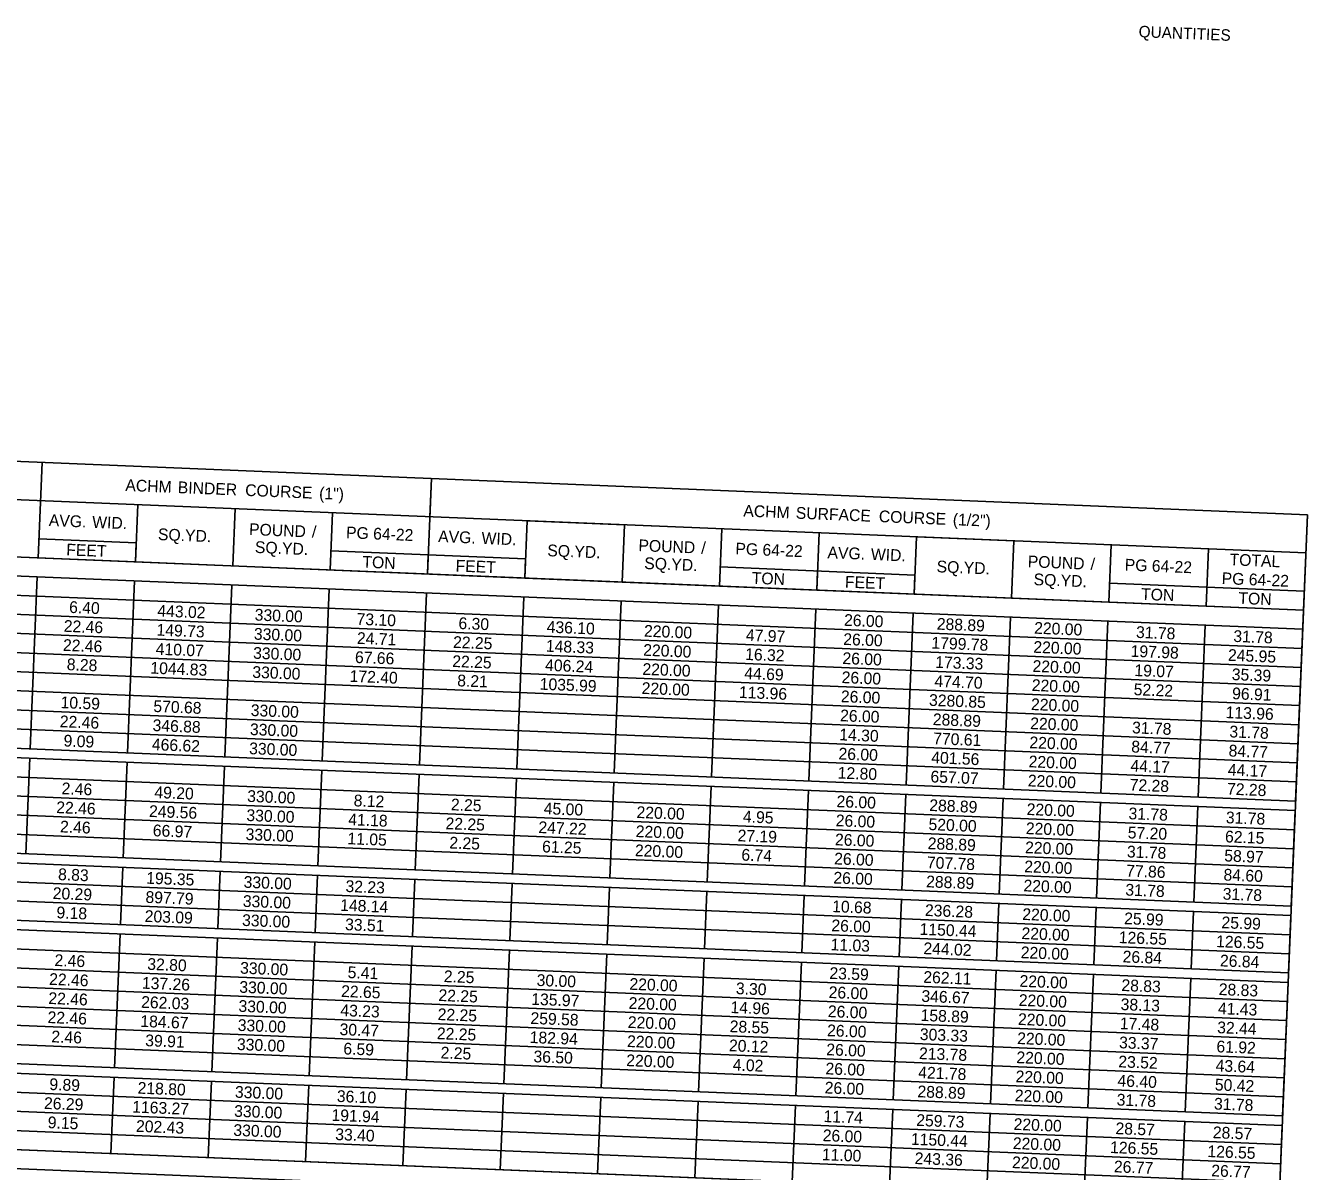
# Model space of a CAD drawing. Extents: x 1164179 to 1171425, y 1655958 to 1657208.
# Drawn here: x 1168859 to 1169513, y 1656436 to 1657021 of the extents above; entities that cross this region are included whole.
import ezdxf

# ---------------------------------------------------------------- set-up
doc = ezdxf.new("R2010")
doc.units = 0
doc.layers.add('Default', color=7, linetype='Continuous')
doc.layers.add('R_Grid', color=7, linetype='Continuous')

msp = doc.modelspace()

# ---------------------------------------------------------------- linework, layer by layer
at = {"layer": 'Default'}
for p, q in [((1168026.37, 1656832.93), (1169513.44, 1656771.41)), ((1168865.55, 1656749.42), (1168867.57, 1656798.13)), ((1168419.62, 1656797.14), (1169512.63, 1656751.93)), ((1168024.36, 1656784.22), (1169511.42, 1656722.7)), ((1169064.28, 1656741.2), (1169066.3, 1656789.91)), ((1169065.49, 1656770.42), (1169066.3, 1656789.91)), ((1168023.96, 1656774.48), (1169511.02, 1656712.96)), ((1168915.23, 1656747.37), (1168916.44, 1656776.59)), ((1168964.92, 1656745.31), (1168966.13, 1656774.54)), ((1169014.6, 1656743.25), (1169015.81, 1656772.48)), ((1169491.27, 1656235.62), (1169513.44, 1656771.41)), ((1169507.39, 1656625.29), (1169513.44, 1656771.41)), ((1168023.55, 1656764.74), (1169510.62, 1656703.22)), ((1169113.96, 1656739.14), (1169115.17, 1656768.37)), ((1169115.17, 1656768.37), (1169164.86, 1656766.31)), ((1169163.65, 1656737.09), (1169164.86, 1656766.31)), ((1168865.95, 1656759.16), (1168915.64, 1656757.11)), ((1169213.33, 1656735.03), (1169214.54, 1656764.26)), ((1169263.01, 1656732.98), (1169264.22, 1656762.2)), ((1169312.69, 1656730.92), (1169313.9, 1656760.15)), ((1169313.9, 1656760.15), (1169363.59, 1656758.09)), ((1169362.38, 1656728.87), (1169363.59, 1656758.09)), ((1168023.15, 1656754.99), (1169510.22, 1656693.48)), ((1168766.19, 1656753.53), (1168915.23, 1656747.37)), ((1168915.23, 1656747.37), (1168915.64, 1656757.11)), ((1169015, 1656753), (1169114.37, 1656748.89)), ((1169412.06, 1656726.81), (1169413.27, 1656756.04)), ((1169461.74, 1656724.76), (1169462.95, 1656753.98)), ((1168022.75, 1656745.25), (1169509.81, 1656683.74)), ((1168915.23, 1656747.37), (1169113.96, 1656739.14)), ((1169064.28, 1656741.2), (1169064.68, 1656750.94)), ((1169113.96, 1656739.14), (1169114.37, 1656748.89)), ((1168861.52, 1656652), (1168865.15, 1656739.68)), ((1168861.52, 1656652), (1168865.15, 1656739.68)), ((1169113.96, 1656739.14), (1169312.69, 1656730.92)), ((1169213.73, 1656744.78), (1169313.1, 1656740.66)), ((1169263.01, 1656732.98), (1169263.42, 1656742.72)), ((1169312.69, 1656730.92), (1169313.1, 1656740.66)), ((1168022.34, 1656735.51), (1169509.41, 1656673.99)), ((1168911.2, 1656649.95), (1168914.83, 1656737.62)), ((1168911.2, 1656649.95), (1168914.83, 1656737.62)), ((1168960.89, 1656647.89), (1168964.51, 1656735.57)), ((1168960.89, 1656647.89), (1168964.51, 1656735.57)), ((1169010.57, 1656645.84), (1169014.2, 1656733.51)), ((1169010.57, 1656645.84), (1169014.2, 1656733.51)), ((1169412.46, 1656736.55), (1169511.83, 1656732.44)), ((1168021.94, 1656725.77), (1169509.01, 1656664.25)), ((1169060.25, 1656643.78), (1169063.88, 1656731.46)), ((1169060.25, 1656643.78), (1169063.88, 1656731.46)), ((1169109.93, 1656641.73), (1169113.56, 1656729.4)), ((1169109.93, 1656641.73), (1169113.56, 1656729.4)), ((1169159.62, 1656639.67), (1169163.24, 1656727.35)), ((1169159.62, 1656639.67), (1169163.24, 1656727.35)), ((1169209.3, 1656637.62), (1169212.93, 1656725.29)), ((1169209.3, 1656637.62), (1169212.93, 1656725.29)), ((1169312.69, 1656730.92), (1169511.42, 1656722.7)), ((1169258.98, 1656635.56), (1169262.61, 1656723.24)), ((1169258.98, 1656635.56), (1169262.61, 1656723.24)), ((1169308.66, 1656633.51), (1169312.29, 1656721.18)), ((1169308.66, 1656633.51), (1169312.29, 1656721.18)), ((1169358.35, 1656631.45), (1169361.97, 1656719.13)), ((1169358.35, 1656631.45), (1169361.97, 1656719.13)), ((1168021.54, 1656716.03), (1169508.6, 1656654.51)), ((1169408.03, 1656629.4), (1169411.66, 1656717.07)), ((1169408.03, 1656629.4), (1169411.66, 1656717.07)), ((1169457.71, 1656627.34), (1169461.34, 1656715.02)), ((1169457.71, 1656627.34), (1169461.34, 1656715.02)), ((1168021.13, 1656706.29), (1169508.2, 1656644.77)), ((1168020.73, 1656696.54), (1169507.8, 1656635.03)), ((1168020.33, 1656686.8), (1169507.39, 1656625.29)), ((1168020.33, 1656686.8), (1169507.39, 1656625.29)), ((1168020.13, 1656681.93), (1169507.19, 1656620.41)), ((1168019.72, 1656672.19), (1169506.79, 1656610.67)), ((1168019.32, 1656662.45), (1169506.39, 1656600.93)), ((1168018.92, 1656652.71), (1169505.98, 1656591.19)), ((1168859.31, 1656598.42), (1168861.32, 1656647.13)), ((1168859.31, 1656598.42), (1168861.32, 1656647.13)), ((1168018.52, 1656642.97), (1169505.58, 1656581.45)), ((1168908.99, 1656596.37), (1168911, 1656645.08)), ((1168908.99, 1656596.37), (1168911, 1656645.08)), ((1168958.67, 1656594.31), (1168960.69, 1656643.02)), ((1168958.67, 1656594.31), (1168960.69, 1656643.02)), ((1169008.35, 1656592.26), (1169010.37, 1656640.97)), ((1169008.35, 1656592.26), (1169010.37, 1656640.97)), ((1169058.04, 1656590.2), (1169060.05, 1656638.91)), ((1169058.04, 1656590.2), (1169060.05, 1656638.91)), ((1169107.72, 1656588.15), (1169109.73, 1656636.86)), ((1169107.72, 1656588.15), (1169109.73, 1656636.86)), ((1169157.4, 1656586.09), (1169159.42, 1656634.8)), ((1169157.4, 1656586.09), (1169159.42, 1656634.8)), ((1168017.91, 1656628.35), (1169504.98, 1656566.84)), ((1168018.11, 1656633.22), (1169505.18, 1656571.71)), ((1169207.08, 1656584.04), (1169209.1, 1656632.75)), ((1169207.08, 1656584.04), (1169209.1, 1656632.75)), ((1169256.77, 1656581.98), (1169258.78, 1656630.69)), ((1169256.77, 1656581.98), (1169258.78, 1656630.69)), ((1169306.45, 1656579.93), (1169308.46, 1656628.64)), ((1169306.45, 1656579.93), (1169308.46, 1656628.64)), ((1169356.13, 1656577.87), (1169358.15, 1656626.58)), ((1169356.13, 1656577.87), (1169358.15, 1656626.58)), ((1169405.81, 1656575.82), (1169407.83, 1656624.53)), ((1169405.81, 1656575.82), (1169407.83, 1656624.53)), ((1169455.5, 1656573.76), (1169457.51, 1656622.47)), ((1169455.5, 1656573.76), (1169457.51, 1656622.47)), ((1168017.51, 1656618.61), (1169504.57, 1656557.09)), ((1168362.48, 1656618.98), (1169505.18, 1656571.71)), ((1169505.18, 1656571.71), (1169507.19, 1656620.41)), ((1168017.11, 1656608.87), (1169504.17, 1656547.35)), ((1168016.7, 1656599.13), (1169503.77, 1656537.61)), ((1168016.5, 1656594.26), (1169503.57, 1656532.74)), ((1168907.58, 1656562.27), (1168908.79, 1656591.5)), ((1168907.58, 1656562.27), (1168908.79, 1656591.5)), ((1168957.26, 1656560.22), (1168958.47, 1656589.44)), ((1168957.26, 1656560.22), (1168958.47, 1656589.44)), ((1168016.1, 1656584.52), (1169503.16, 1656523)), ((1168361.07, 1656584.88), (1169503.77, 1656537.61)), ((1169006.94, 1656558.16), (1169008.15, 1656587.39)), ((1169006.94, 1656558.16), (1169008.15, 1656587.39)), ((1169056.63, 1656556.11), (1169057.83, 1656585.33)), ((1169056.63, 1656556.11), (1169057.83, 1656585.33)), ((1169106.31, 1656554.05), (1169107.52, 1656583.28)), ((1169106.31, 1656554.05), (1169107.52, 1656583.28)), ((1168015.69, 1656574.77), (1169502.76, 1656513.26)), ((1169155.99, 1656552), (1169157.2, 1656581.22)), ((1169155.99, 1656552), (1169157.2, 1656581.22)), ((1169205.67, 1656549.94), (1169206.88, 1656579.17)), ((1169205.67, 1656549.94), (1169206.88, 1656579.17)), ((1169255.36, 1656547.89), (1169256.56, 1656577.11)), ((1169255.36, 1656547.89), (1169256.56, 1656577.11)), ((1169305.04, 1656545.83), (1169306.25, 1656575.06)), ((1169305.04, 1656545.83), (1169306.25, 1656575.06)), ((1169354.72, 1656543.78), (1169355.93, 1656573)), ((1169354.72, 1656543.78), (1169355.93, 1656573)), ((1169404.4, 1656541.72), (1169405.61, 1656570.95)), ((1169404.4, 1656541.72), (1169405.61, 1656570.95)), ((1169454.09, 1656539.67), (1169455.29, 1656568.89)), ((1169454.09, 1656539.67), (1169455.29, 1656568.89)), ((1168015.29, 1656565.03), (1169502.36, 1656503.51)), ((1169503.77, 1656537.61), (1169504.98, 1656566.84)), ((1168014.89, 1656555.29), (1169501.95, 1656493.77)), ((1168904.56, 1656489.21), (1168907.38, 1656557.4)), ((1168904.56, 1656489.21), (1168907.38, 1656557.4)), ((1168954.24, 1656487.16), (1168957.06, 1656555.35)), ((1168954.24, 1656487.16), (1168957.06, 1656555.35)), ((1169003.92, 1656485.1), (1169006.74, 1656553.29)), ((1169003.92, 1656485.1), (1169006.74, 1656553.29)), ((1169053.6, 1656483.05), (1169056.42, 1656551.24)), ((1169053.6, 1656483.05), (1169056.42, 1656551.24)), ((1169103.29, 1656480.99), (1169106.11, 1656549.18)), ((1169103.29, 1656480.99), (1169106.11, 1656549.18)), ((1168014.49, 1656545.55), (1169501.55, 1656484.03)), ((1169152.97, 1656478.93), (1169155.79, 1656547.13)), ((1169152.97, 1656478.93), (1169155.79, 1656547.13)), ((1169202.65, 1656476.88), (1169205.47, 1656545.07)), ((1169202.65, 1656476.88), (1169205.47, 1656545.07)), ((1169252.33, 1656474.82), (1169255.15, 1656543.02)), ((1169252.33, 1656474.82), (1169255.15, 1656543.02)), ((1168014.08, 1656535.81), (1169501.15, 1656474.29)), ((1169302.02, 1656472.77), (1169304.84, 1656540.96)), ((1169302.02, 1656472.77), (1169304.84, 1656540.96)), ((1169351.7, 1656470.71), (1169354.52, 1656538.91)), ((1169351.7, 1656470.71), (1169354.52, 1656538.91)), ((1169401.38, 1656468.66), (1169404.2, 1656536.85)), ((1169401.38, 1656468.66), (1169404.2, 1656536.85)), ((1169451.06, 1656466.6), (1169453.88, 1656534.79)), ((1169451.06, 1656466.6), (1169453.88, 1656534.79)), ((1169500.75, 1656464.55), (1169503.57, 1656532.74)), ((1168013.68, 1656526.07), (1169500.75, 1656464.55)), ((1168013.48, 1656521.19), (1169500.54, 1656459.68)), ((1168013.08, 1656511.45), (1169500.14, 1656449.94)), ((1168358.05, 1656511.82), (1169500.75, 1656464.55)), ((1168012.67, 1656501.71), (1169499.74, 1656440.19)), ((1168012.27, 1656491.97), (1169499.33, 1656430.45)), ((1168902.74, 1656445.37), (1168904.35, 1656484.34)), ((1168902.74, 1656445.37), (1168904.35, 1656484.34)), ((1168011.87, 1656482.23), (1169498.93, 1656420.71)), ((1168952.42, 1656443.32), (1168954.04, 1656482.29)), ((1168952.42, 1656443.32), (1168954.04, 1656482.29)), ((1169002.11, 1656441.26), (1169003.72, 1656480.23)), ((1169002.11, 1656441.26), (1169003.72, 1656480.23)), ((1169051.79, 1656439.21), (1169053.4, 1656478.17)), ((1169051.79, 1656439.21), (1169053.4, 1656478.17)), ((1168011.46, 1656472.49), (1169498.53, 1656410.97)), ((1169101.47, 1656437.15), (1169103.08, 1656476.12)), ((1169101.47, 1656437.15), (1169103.08, 1656476.12)), ((1169151.15, 1656435.1), (1169152.77, 1656474.06)), ((1169151.15, 1656435.1), (1169152.77, 1656474.06)), ((1169200.84, 1656433.04), (1169202.45, 1656472.01)), ((1169200.84, 1656433.04), (1169202.45, 1656472.01)), ((1169250.52, 1656430.99), (1169252.13, 1656469.95)), ((1169250.52, 1656430.99), (1169252.13, 1656469.95)), ((1169300.2, 1656428.93), (1169301.81, 1656467.9)), ((1169300.2, 1656428.93), (1169301.81, 1656467.9)), ((1169349.88, 1656426.88), (1169351.5, 1656465.84)), ((1169349.88, 1656426.88), (1169351.5, 1656465.84)), ((1169399.57, 1656424.82), (1169401.18, 1656463.79)), ((1169399.57, 1656424.82), (1169401.18, 1656463.79)), ((1169449.25, 1656422.77), (1169450.86, 1656461.73)), ((1169449.25, 1656422.77), (1169450.86, 1656461.73)), ((1169497.32, 1656381.74), (1169500.54, 1656459.68)), ((1168853.06, 1656447.43), (1169300.2, 1656428.93))]:
    msp.add_line(p, q, dxfattribs=at)

# ---------------------------------------------------------------- texts
for s, p in [('ACHM', (1168910.02, 1656783.61)), (' BINDER', (1168934.55, 1656782.6)), (' COURSE', (1168968.95, 1656781.17)), (' (1")', (1169006.7, 1656779.61)), ('AVG.', (1168870.95, 1656765.71)), ('ACHM', (1169225.46, 1656770.56)), (' SURFACE', (1169249.99, 1656769.55)), (' COURSE', (1169292.39, 1656767.79)), (' (1/2")', (1169330.14, 1656766.23)), (' WID.', (1168890.85, 1656764.89)), ('SQ.YD.', (1168926.65, 1656758.53)), ('POUND', (1168973.18, 1656761.11)), (' /', (1169003.01, 1656759.87)), ('PG', (1169022.67, 1656759.44)), (' 64-22', (1169034.26, 1656758.96)), ('SQ.YD.', (1168976.14, 1656751.98)), ('AVG.', (1169069.68, 1656757.49)), (' WID.', (1169089.58, 1656756.67)), ('POUND', (1169171.91, 1656752.89)), ('FEET', (1168879.85, 1656750.71)), ('SQ.YD.', (1169125.38, 1656750.31)), (' /', (1169201.74, 1656751.65)), ('PG', (1169221.4, 1656751.21)), (' 64-22', (1169232.99, 1656750.73)), ('AVG.', (1169268.41, 1656749.27)), (' WID.', (1169288.31, 1656748.45)), ('TOTAL', (1169473.63, 1656745.66)), ('TON', (1169031.01, 1656744.45)), ('FEET', (1169078.58, 1656742.48)), ('SQ.YD.', (1169174.87, 1656743.76)), ('SQ.YD.', (1169324.11, 1656742.09)), ('POUND', (1169370.64, 1656744.67)), (' /', (1169400.47, 1656743.43)), ('PG', (1169420.13, 1656742.99)), (' 64-22', (1169431.72, 1656742.51)), ('TON', (1169229.74, 1656736.23)), ('FEET', (1169277.31, 1656734.26)), ('SQ.YD.', (1169373.6, 1656735.53)), ('PG', (1169469.61, 1656736.07)), (' 64-22', (1169481.2, 1656735.59)), ('TON', (1169428.47, 1656728.01)), ('TON', (1169478.16, 1656725.95)), ('6.40', (1168881.32, 1656721.37)), ('443.02', (1168926.36, 1656719.51)), ('330.00', (1168976.02, 1656717.45)), ('73.10', (1169028.04, 1656715.3)), ('6.30', (1169080.05, 1656713.15)), ('26.00', (1169276.85, 1656714.77)), ('288.89', (1169324.19, 1656712.81)), ('22.46', (1168878.57, 1656711.73)), ('149.73', (1168925.93, 1656709.77)), ('330.00', (1168975.62, 1656707.71)), ('436.10', (1169125.07, 1656711.29)), ('220.00', (1169174.75, 1656709.23)), ('47.97', (1169226.75, 1656707.08)), ('220.00', (1169373.89, 1656710.75)), ('31.78', (1169425.88, 1656708.6)), ('31.78', (1169475.56, 1656706.55)), ('22.46', (1168878.17, 1656701.98)), ('410.07', (1168925.52, 1656700.02)), ('24.71', (1169028.2, 1656705.54)), ('22.25', (1169077.28, 1656703.51)), ('148.33', (1169124.66, 1656701.55)), ('26.00', (1169276.45, 1656705.02)), ('1799.78', (1169321.46, 1656703.16)), ('220.00', (1169373.48, 1656701.01)), ('330.00', (1168975.22, 1656697.97)), ('67.66', (1169027.22, 1656695.82)), ('22.25', (1169076.88, 1656693.76)), ('220.00', (1169174.35, 1656699.49)), ('16.32', (1169226.38, 1656697.34)), ('26.00', (1169276.04, 1656695.28)), ('173.33', (1169323.39, 1656693.32)), ('197.98', (1169423.15, 1656698.96)), ('245.95', (1169472.82, 1656696.9)), ('8.28', (1168880.09, 1656692.15)), ('1044.83', (1168922.79, 1656690.38)), ('330.00', (1168974.82, 1656688.23)), ('406.24', (1169124.27, 1656691.8)), ('220.00', (1169173.95, 1656689.75)), ('44.69', (1169225.94, 1656687.6)), ('220.00', (1169373.08, 1656691.27)), ('19.07', (1169425.08, 1656689.12)), ('35.39', (1169474.76, 1656687.06)), ('172.40', (1169024.5, 1656686.17)), ('8.21', (1169079.41, 1656683.9)), ('1035.99', (1169121.52, 1656682.16)), ('220.00', (1169173.55, 1656680.01)), ('26.00', (1169275.64, 1656685.54)), ('474.70', (1169323, 1656683.58)), ('220.00', (1169372.68, 1656681.53)), ('113.96', (1169223.22, 1656677.95)), ('26.00', (1169275.24, 1656675.8)), ('3280.85', (1169320.23, 1656673.94)), ('52.22', (1169424.71, 1656679.37)), ('96.91', (1169474.94, 1656677.3)), ('10.59', (1168876.96, 1656672.76)), ('570.68', (1168924.31, 1656670.8)), ('330.00', (1168974.01, 1656668.74)), ('220.00', (1169372.28, 1656671.78)), ('113.96', (1169471.63, 1656667.67)), ('22.46', (1168876.56, 1656663.02)), ('346.88', (1168923.91, 1656661.06)), ('26.00', (1169274.84, 1656666.06)), ('288.89', (1169322.17, 1656664.1)), ('220.00', (1169371.87, 1656662.04)), ('330.00', (1168973.61, 1656659)), ('14.30', (1169274.43, 1656656.32)), ('770.61', (1169322.36, 1656654.33)), ('31.78', (1169423.87, 1656659.89)), ('31.78', (1169473.55, 1656657.84)), ('9.09', (1168878.48, 1656653.18)), ('466.62', (1168923.54, 1656651.31)), ('330.00', (1168973.2, 1656649.26)), ('220.00', (1169371.47, 1656652.3)), ('84.77', (1169423.47, 1656650.15)), ('84.77', (1169473.15, 1656648.1)), ('26.00', (1169274.03, 1656646.57)), ('401.56', (1169321.37, 1656644.62)), ('220.00', (1169371.07, 1656642.56)), ('12.80', (1169273.63, 1656636.83)), ('657.07', (1169320.97, 1656634.87)), ('44.17', (1169423.07, 1656640.41)), ('44.17', (1169472.75, 1656638.35)), ('2.46', (1168877.48, 1656628.82)), ('220.00', (1169370.66, 1656632.82)), ('72.28', (1169422.66, 1656630.67)), ('72.28', (1169472.34, 1656628.61)), ('49.20', (1168924.84, 1656626.87)), ('330.00', (1168972.2, 1656624.91)), ('8.12', (1169026.56, 1656622.66)), ('26.00', (1169273.02, 1656622.22)), ('22.46', (1168874.74, 1656619.18)), ('249.56', (1168922.1, 1656617.22)), ('330.00', (1168971.79, 1656615.16)), ('2.25', (1169076.18, 1656620.6)), ('45.00', (1169123.57, 1656618.64)), ('220.00', (1169170.93, 1656616.69)), ('288.89', (1169320.36, 1656620.26)), ('220.00', (1169370.06, 1656618.21)), ('31.78', (1169422.05, 1656616.05)), ('2.46', (1168876.67, 1656609.34)), ('41.18', (1169023.79, 1656613.01)), ('22.25', (1169073.45, 1656610.96)), ('247.22', (1169120.86, 1656609)), ('4.95', (1169225.23, 1656614.44)), ('26.00', (1169272.62, 1656612.48)), ('520.00', (1169319.97, 1656610.52)), ('220.00', (1169369.66, 1656608.46)), ('31.78', (1169471.74, 1656614)), ('66.97', (1168924.02, 1656607.38)), ('330.00', (1168971.39, 1656605.42)), ('11.05', (1169023.37, 1656603.27)), ('220.00', (1169170.52, 1656606.94)), ('27.19', (1169222.52, 1656604.79)), ('26.00', (1169272.22, 1656602.74)), ('57.20', (1169421.67, 1656606.31)), ('62.15', (1169471.32, 1656604.26)), ('2.25', (1169075.38, 1656601.12)), ('61.25', (1169122.73, 1656599.16)), ('220.00', (1169170.12, 1656597.2)), ('6.74', (1169224.46, 1656594.95)), ('288.89', (1169319.55, 1656600.78)), ('220.00', (1169369.25, 1656598.72)), ('31.78', (1169421.25, 1656596.57)), ('26.00', (1169271.81, 1656593)), ('707.78', (1169319.15, 1656591.04)), ('220.00', (1169368.85, 1656588.98)), ('58.97', (1169470.93, 1656594.52)), ('8.83', (1168875.66, 1656584.99)), ('195.35', (1168920.67, 1656583.13)), ('26.00', (1169271.41, 1656583.25)), ('77.86', (1169420.85, 1656586.83)), ('84.60', (1169470.54, 1656584.77)), ('20.29', (1168872.93, 1656575.34)), ('330.00', (1168970.38, 1656581.07)), ('32.23', (1169022.38, 1656578.92)), ('288.89', (1169318.75, 1656581.3)), ('220.00', (1169368.45, 1656579.24)), ('31.78', (1169420.44, 1656577.09)), ('897.79', (1168920.28, 1656573.38)), ('330.00', (1168969.98, 1656571.33)), ('148.14', (1169019.66, 1656569.27)), ('31.78', (1169470.12, 1656575.03)), ('9.18', (1168874.85, 1656565.5)), ('203.09', (1168919.88, 1656563.64)), ('10.68', (1169270.79, 1656568.64)), ('236.28', (1169318.14, 1656566.68)), ('220.00', (1169367.84, 1656564.63)), ('25.99', (1169419.84, 1656562.48)), ('330.00', (1168969.58, 1656561.59)), ('33.51', (1169022.16, 1656559.41)), ('26.00', (1169270.4, 1656558.9)), ('1150.44', (1169315.43, 1656557.04)), ('25.99', (1169469.52, 1656560.42)), ('220.00', (1169367.44, 1656554.88)), ('126.55', (1169417.09, 1656552.83)), ('126.55', (1169466.77, 1656550.78)), ('11.03', (1169269.99, 1656549.16)), ('244.02', (1169317.37, 1656547.2)), ('220.00', (1169367.04, 1656545.14)), ('26.84', (1169419.05, 1656542.99)), ('2.46', (1168873.85, 1656541.15)), ('32.80', (1168921.21, 1656539.19)), ('330.00', (1168968.57, 1656537.23)), ('26.84', (1169468.73, 1656540.94)), ('22.46', (1168871.12, 1656531.5)), ('5.41', (1169023.48, 1656534.96)), ('2.25', (1169072.56, 1656532.93)), ('30.00', (1169119.94, 1656530.97)), ('23.59', (1169269.38, 1656534.55)), ('262.11', (1169317.32, 1656532.56)), ('220.00', (1169366.43, 1656530.53)), ('137.26', (1168918.47, 1656529.55)), ('330.00', (1168968.17, 1656527.49)), ('22.65', (1169020.14, 1656525.34)), ('22.25', (1169069.83, 1656523.28)), ('220.00', (1169167.3, 1656529.01)), ('3.30', (1169221.64, 1656526.76)), ('26.00', (1169268.99, 1656524.8)), ('28.83', (1169418.43, 1656528.38)), ('28.83', (1169468.11, 1656526.32)), ('22.46', (1168870.71, 1656521.76)), ('262.03', (1168918.07, 1656519.8)), ('330.00', (1168967.76, 1656517.75)), ('135.97', (1169117.2, 1656521.32)), ('220.00', (1169166.9, 1656519.27)), ('14.96', (1169218.9, 1656517.12)), ('346.67', (1169316.34, 1656522.84)), ('220.00', (1169366.03, 1656520.79)), ('38.13', (1169418.03, 1656518.64)), ('41.43', (1169467.71, 1656516.58)), ('22.46', (1168870.31, 1656512.02)), ('184.67', (1168917.67, 1656510.06)), ('43.23', (1169019.76, 1656515.6)), ('22.25', (1169069.42, 1656513.54)), ('259.58', (1169116.79, 1656511.58)), ('26.00', (1169268.59, 1656515.06)), ('158.89', (1169315.93, 1656513.1)), ('220.00', (1169365.63, 1656511.05)), ('330.00', (1168967.36, 1656508.01)), ('30.47', (1169019.36, 1656505.86)), ('22.25', (1169069.02, 1656503.8)), ('220.00', (1169166.49, 1656509.53)), ('28.55', (1169218.47, 1656507.38)), ('26.00', (1169268.19, 1656505.32)), ('303.33', (1169315.53, 1656503.36)), ('17.48', (1169417.62, 1656508.9)), ('32.44', (1169467.32, 1656506.84)), ('2.46', (1168872.24, 1656502.18)), ('39.91', (1168920.17, 1656500.2)), ('330.00', (1168966.96, 1656498.26)), ('182.94', (1169116.41, 1656501.84)), ('220.00', (1169166.09, 1656499.79)), ('20.12', (1169218.12, 1656497.63)), ('220.00', (1169365.22, 1656501.31)), ('33.37', (1169417.22, 1656499.15)), ('61.92', (1169466.94, 1656497.1)), ('6.59', (1169021.28, 1656496.02)), ('2.25', (1169070.94, 1656493.96)), ('36.50', (1169118.33, 1656492)), ('26.00', (1169267.78, 1656495.58)), ('213.78', (1169315.12, 1656493.62)), ('220.00', (1169364.82, 1656491.56)), ('220.00', (1169165.69, 1656490.04)), ('4.02', (1169220.05, 1656487.79)), ('26.00', (1169267.38, 1656485.84)), ('421.78', (1169314.72, 1656483.88)), ('23.52', (1169416.85, 1656489.41)), ('43.64', (1169466.52, 1656487.36)), ('9.89', (1168871.22, 1656477.83)), ('220.00', (1169364.42, 1656481.82)), ('46.40', (1169416.43, 1656479.67)), ('50.42', (1169466.13, 1656477.61)), ('218.80', (1168916.27, 1656475.97)), ('330.00', (1168965.95, 1656473.91)), ('36.10', (1169017.96, 1656471.76)), ('26.00', (1169266.98, 1656476.1)), ('288.89', (1169314.32, 1656474.14)), ('220.00', (1169364.01, 1656472.08)), ('26.29', (1168868.49, 1656468.18)), ('1163.27', (1168913.52, 1656466.32)), ('330.00', (1168965.55, 1656464.17)), ('31.78', (1169416.01, 1656469.93)), ('31.78', (1169465.69, 1656467.87)), ('9.15', (1168870.4, 1656458.35)), ('191.94', (1169015.23, 1656462.11)), ('11.74', (1169266.38, 1656461.48)), ('259.73', (1169313.72, 1656459.52)), ('202.43', (1168915.45, 1656456.48)), ('330.00', (1168965.14, 1656454.43)), ('33.40', (1169017.15, 1656452.28)), ('26.00', (1169265.97, 1656451.74)), ('220.00', (1169363.41, 1656457.47)), ('28.57', (1169415.41, 1656455.32)), ('28.57', (1169465.09, 1656453.26)), ('1150.44', (1169311, 1656449.88)), ('220.00', (1169363.01, 1656447.73)), ('126.55', (1169412.66, 1656445.67)), ('11.00', (1169265.57, 1656442)), ('243.36', (1169312.91, 1656440.04)), ('220.00', (1169362.6, 1656437.98)), ('126.55', (1169462.34, 1656443.62)), ('26.77', (1169414.6, 1656435.83)), ('26.77', (1169464.29, 1656433.78))]:
    msp.add_text(s, height=6, rotation=357.63112, dxfattribs=at).set_placement(p)
at = {"layer": 'R_Grid'}
msp.add_text('QUANTITIES', height=5.862, rotation=357.63112, dxfattribs=at).set_placement((1169427.22, 1657015.22))

doc.saveas('drawing.dxf')
